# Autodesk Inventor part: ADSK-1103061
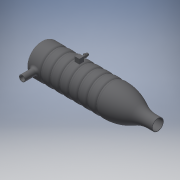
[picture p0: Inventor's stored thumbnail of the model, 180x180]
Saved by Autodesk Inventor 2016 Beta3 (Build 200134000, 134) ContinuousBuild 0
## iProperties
Shininess: 50.0
Length Units: 11272
Angle Units: 11279
Time Units: 11290
Mass Units: 11286
Length Display Precision: 4
Angle Display Precision: 2
Compacted: True
Created: 2000-08
Part Number: ADSK-1103061
Document SubType Name: Modeling
Description: EXHAUST PIPE - SIDE
Mass: 7.18318 g
Surface Area: 233.725 cm^2
Volume: 7.18318 cm^3
Density: 1 g/cm^3
Material: Generic
Appearance: Black
Density: 0.0
Volumn: 0.0
Area: 0.0
PropertySet Name: Model Information
Control State: 0
Master: False
Checked Out: False
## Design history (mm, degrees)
node "Revolution1" dims "d8" = 90 deg
  sketch "Sketch3"
    geometry: L1 (33.387, 39.395)-(33.387, -87.605); L2 (49.262, -64.093)-(49.262, -4.86); L3 (39.387, 32.722)-(39.387, 39.395); L4 (39.387, 39.395)-(33.387, 39.395); L5 (33.387, -87.605)-(36.562, -87.605); L6 (36.562, -87.605)-(49.262, -79.35); L7 (49.262, -79.35)-(49.262, -64.093); L8 (42.607, 20.345)-(43.458, 18.72); A1 r 25.4 centre (64.787, 32.722) between (39.387, 32.722) and (42.607, 20.345); A2 r 50.8 centre (-1.538, -4.86) between (49.262, -4.86) and (43.458, 18.72); 1 further point
    constraints: 16 end point, 4 point on circle, 3 parallel, 3 tangent, 2 centre point, 2 perpendicular, 2 point on line, 1 vertical, 1 other
    dimensions: "d1" = 6.35 diameter of L5.end L1; "d2" = 31.75 diameter of L2.start L1; "d5" = 8.255 vertical distance of L5.end L6.end; "d6" = 127 distance of L1.start L1.end; "d7" = 12 diameter of L3 L1; "d48" = 25.4 radius of A1; "d49" = 6.67308 distance from line of L4 A1.centre; "d50" = 19.05 distance from line of L4 L8.start; "d51" = 31.75 distance from line of point (49.262, 7.645) L4; "d53" = 50.8 radius of A2
node "Fillet1" dims "d9" = 3.175
workaxis "Work Axis1"
node "Revolution2" dims "d15" = 90 deg
  sketch "Sketch4"
    geometry: L1 (49.262, -4.86)-(49.262, -77.627) reference; L2 (33.387, 64.795)-(33.387, -113.005) reference; L3 (49.262, -6.96)-(48.373, -7.595); L4 (48.373, -7.595)-(48.373, -8.865); L5 (48.373, -8.865)-(49.262, -9.5); L6 (27.387, 39.395)-(39.387, 39.395) reference
    constraints: 6 end point, 2 point on line, 1 equal length, 1 parallel
    dimensions: "d11" = 1.27 distance of L3.end L4.end; "d12" = 2.54 distance of L5.end L3.start; "d13" = 46.355 distance from line of L6 L3.start; "d14" = 14.986 distance between parallel lines of L2 L4
node "Fillet2" dims "d16" = 3.175
node "Rectangular Pattern1" dims "d17" = 70, "d19" = 9.525
workplane "Work Plane1"
workplane "Work Plane2"
node "Extrusion1" dims "d23" = 25.4, "d24" = 0
  sketch "Sketch5"
    geometry: L1 (136.516, 0)-(-41.284, 0) reference; L2 (111.116, 6)-(111.116, -6) reference; C1 r 3.175 at (-0.009, 0)
    constraints: 1 centre point, 1 point on line
    dimensions: "d22" = 6.35 diameter of C1; "d54" = 111.125 distance from line of L2 C1.centre
node "Shell1" dims "d25" = 0.6096
node "Fillet5" dims "d81" = 2.54
workaxis "Work Axis2"
workplane "Work Plane3"
workplane "Work Plane4"
node "Extrusion2" dims "d82" = 0, "d83" = 4.7625 (= d85)
  sketch "Sketch6"
    geometry: L1 (-6.25, 20.108)-(-1.487, 20.108); L2 (-1.487, 20.108)-(-1.487, 24.871); L3 (-1.487, 24.871)-(-6.25, 24.871); L4 (-6.25, 24.871)-(-6.25, 20.108); L5 (-3.869, 128.672)-(-3.869, -49.128) reference
    constraints: 8 end point, 2 parallel, 1 horizontal, 1 perpendicular
    dimensions: "d85" = 4.7625 distance of L1.end L2.end; "d84" = 4.7625 distance of L2.end L3.end (= d85); "d98" = 2.38125 distance between parallel lines of L2 L5 (= 0.5 x d84)
node "Extrusion3" dims "d86" = 0, "d87" = 3.175
  sketch "Sketch7"
    geometry: L1 (4.763, 0)-(4.763, 4.762) reference; L2 (0, 4.762)-(4.763, 4.762) reference; C1 r 1.27 at (2.381, 2.381)
    constraints: 1 centre point
    dimensions: "d88" = 2.54 diameter of C1; "d90" = 2.38125 distance from line of C1.centre L2 (= 0.5 x d85); "d89" = 2.38125 distance from line of L1 C1.centre (= d90)
node "Extrusion4" dims "d91" = -12 deg, "d92" = 3.175
  sketch "Sketch8"
    geometry: C1 r 1.27 at (0, 0) reference; C2 r 1.905 at (0, 0)
    constraints: 1 centre point, 1 coincident
    dimensions: "d93" = 3.81 diameter of C2
node "Extrusion6" dims "d104" = 25.4, "d105" = 0
  sketch "Sketch12"
    geometry: L1 (-6.25, 20.108)-(-6.25, 24.871) reference; L2 (-1.487, 20.108)-(-6.25, 20.108) reference; L3 (-1.487, 24.871)-(-1.487, 20.108) reference; L4 (-6.25, 24.871)-(-1.487, 24.871) reference
node "Extrusion5" dims "d94" = 0, "d95" = 10.795
  sketch "Sketch9"
    geometry: C1 r 1.23 at (0, 0) reference; C2 r 1.048 at (0, 0)
    constraints: 1 centre point, 1 coincident
    dimensions: "d96" = 2.0955 diameter of C2
body "Solid1"
other parameters: "d21" = -12.7
